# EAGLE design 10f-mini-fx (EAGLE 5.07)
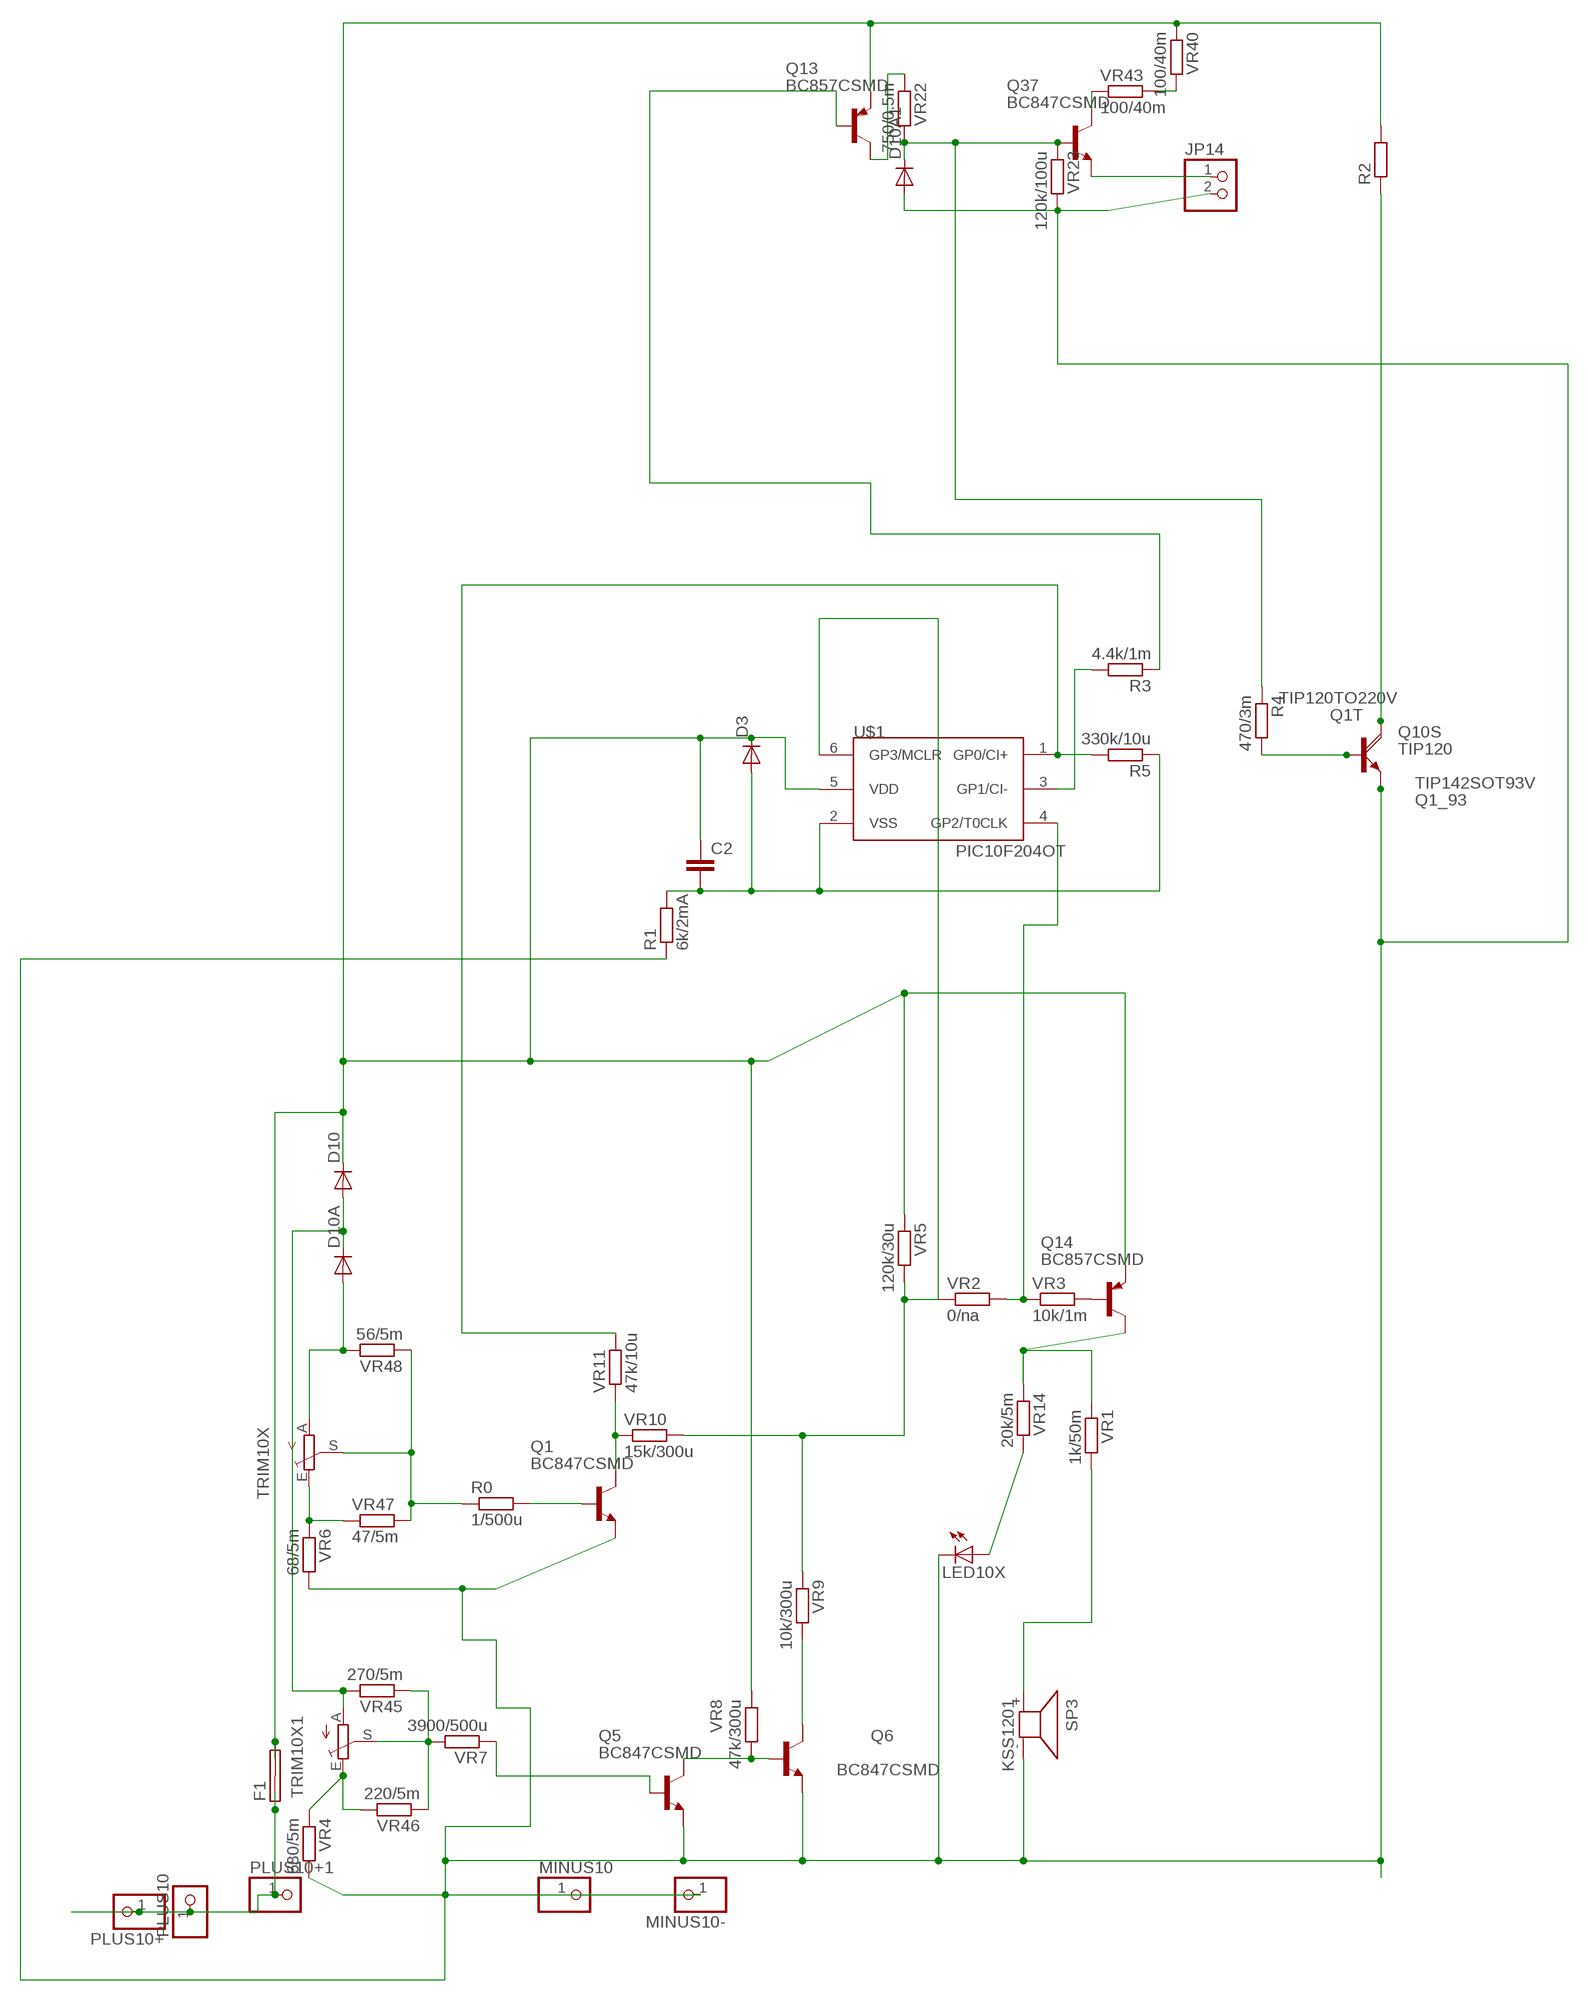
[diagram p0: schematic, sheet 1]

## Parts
C2  C-EUC0805  [C0805]
D3  DIODE-MINIMELF  [MINIMELF]
D10  DIODE-MINIMELF  [MINIMELF]
D10A  DIODE-MINIMELF  [MINIMELF]
D10A1  DIODE-MINIMELF  [MINIMELF]
F1  SHK20L7MM5  [7MM5]
JP14  PINHD-1X2STR  [1X02]
LED10X  LEDCHIPLED_1206  [CHIPLED_1206]
MINUS10  PINHD-1X14.5MM  [1X4MM5]
MINUS10-  PINHD-1X11X0.4  [1X01]
PLUS10  PINHD-1X14.5MM  [1X4MM5]
PLUS10+  PINHD-1X11X0.4  [1X01]
PLUS10+1  PINHD-1X11X0.4  [1X01]
Q1  BC847CSMD  [SOT23]
Q1_93  TIP142SOT93V  [SOT93V]
Q1T  TIP120TO220V  [TO220AV]
Q5  BC847CSMD  [SOT23]
Q6  BC847CSMD  [SOT23]
Q10S  TIP120  TIP120DPAK  [D-PAK_TO252AA]
Q13  BC857CSMD  [SOT23-BEC]
Q14  BC857CSMD  [SOT23-BEC]
Q37  BC847CSMD  [SOT23]
R0  1/500u  R-EU_R1206  [R1206]
R1  6k/2mA  R-EU_R0805  [R0805]
R2  R-EU_CERAM35  [CERAM35]
R3  4.4k/1m  R-EU_R1206  [R1206]
R4  470/3m  R-EU_R1206  [R1206]
R5  330k/10u  R-EU_R0805  [R0805]
SP3  KSS1201  KSS12017MM  [KSS1202]
TRIM10X  TRIM_EU-S64W  [S64W]
TRIM10X1  TRIM_EU-S64W  [S64W]
U$1  PIC10F204OT  [SOT23-6]
VR1  1k/50m  R-EU_R0805  [R0805]
VR2  0/na  R-EU_R0805  [R0805]
VR3  10k/1m  R-EU_R1206  [R1206]
VR4  680/5m  R-EU_R1206  [R1206]
VR5  120k/30u  R-EU_R0805  [R0805]
VR6  68/5m  R-EU_R1206  [R1206]
VR7  3900/500u  R-EU_M1206  [M1206]
VR8  47k/300u  R-EU_R1206  [R1206]
VR9  10k/300u  R-EU_R0805  [R0805]
VR10  15k/300u  R-EU_R1206  [R1206]
VR11  47k/10u  R-EU_R0805  [R0805]
VR14  20k/5m  R-EU_R0805  [R0805]
VR22  750/0.5m  R-EU_R0805  [R0805]
VR23  120k/100u  R-EU_R0805  [R0805]
VR40  100/40m  R-EU_R1206  [R1206]
VR43  100/40m  R-EU_R1206  [R1206]
VR45  270/5m  R-EU_R0805  [R0805]
VR46  220/5m  R-EU_R1206  [R1206]
VR47  47/5m  R-EU_R0805  [R0805]
VR48  56/5m  R-EU_R0805  [R0805]

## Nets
B: R0.1 TRIM10X.S VR47.2 VR48.1
BUZZ+: SP3.+ VR1.2
FPLUS: C2.1 D3.C D10.C F1.2A F1.2B Q13.E Q14.E R2.2 U$1.5(VDD) VR5.1 VR8.1 VR40.1
GP3: U$1.4(GP2/T0CLK) VR2.2 VR3.1
INPLUS: F1.1A F1.1B PLUS10+1.1 PLUS10+.1 PLUS10.1
N$1: R3.2 U$1.3(GP1/CI-)
N$2: Q1.3(C) VR10.1 VR11.1
N$3: Q5.3(C) Q6.1(B) VR8.2
N$4: LED10X.A VR14.2
N$5: Q6.3(C) VR9.2
N$6: U$1.6(GP3/MCLR) VR2.1 VR5.2 VR9.1 VR10.2
N$7: Q1.1(B) R0.2
N$8: Q14.C VR1.1 VR14.1
N$10: Q14.B VR3.2
N$14: D10A.A TRIM10X.A VR48.2
N$17: D10.A D10A.C TRIM10X1.A VR45.2
N$22: TRIM10X1.S VR7.2 VR45.1 VR46.1
N$23: Q13.B R3.1
N$24: TRIM10X1.E VR4.1 VR46.2
N$25: Q1_93.B Q1T.B Q10S.1(B) R4.2
N$128: TRIM10X.E VR6.1 VR47.1
N$136: JP14.1 Q37.2(E)
N$138: R5.2 U$1.1(GP0/CI+) VR11.2
N$159: Q13.C VR22.1
N$163: VR40.2 VR43.2
N$164: Q37.3(C) VR43.1
N$168: Q5.1(B) VR7.1
N$179: D10A1.C Q37.1(B) R4.1 VR22.2 VR23.1
Q10C: Q1_93.C Q1T.C Q10S.4(C) R2.1
VSS: D10A1.A JP14.2 LED10X.C MINUS10-.1 MINUS10.1 Q1.2(E) Q1_93.E Q1T.E Q5.2(E) Q6.2(E) Q10S.3(E) R1.1 SP3.- VR4.2 VR6.2 VR23.2
VSS1: C2.2 D3.A R1.2 R5.1 U$1.2(VSS)

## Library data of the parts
C2 = rcl:C-EU: CAPACITOR, European symbol
D3 D10 D10A D10A1 = diode:DIODE-: DIODE
F1 = fuse:SHK20L: FUSE HOLDER 5 x 20 mm, SH contact, SHH1 Schukat, E1073 Buerklin
JP14 = pinhead:PINHD-1X2: PIN HEADER
LED10X = led:LED: LED
MINUS10 MINUS10- PLUS10 PLUS10+ PLUS10+1 = pinhead:PINHD-1X1: PIN HEADER
Q1 Q5 Q6 Q37 = transistor-npn:BC847*: NPN Transistor
Q1_93 = transistor-power:TIP142: NPN DARLINGTON TRANSISTOR
Q1T Q10S = transistor-power:TIP120: NPN DARLINGTON TRANSISTOR
Q13 Q14 = transistor-pnp:BC857*: PNP Transistror
R0 R1 R3-R5 VR1-VR11 VR14 VR22 VR23 VR40 VR43 VR45-VR48 = rcl-2:R-EU_: RESISTOR, European symbol
R2 = rcl:R-EU_: RESISTOR, European symbol
SP3 = buzzer:KSS1201: SPEAKER
TRIM10X TRIM10X1 = pot:TRIM_EU-: POTENTIOMETER
U$1 = microchip-3:PIC10F2*: uPC nW 0,25/0,5k Program Flash memory Comparator

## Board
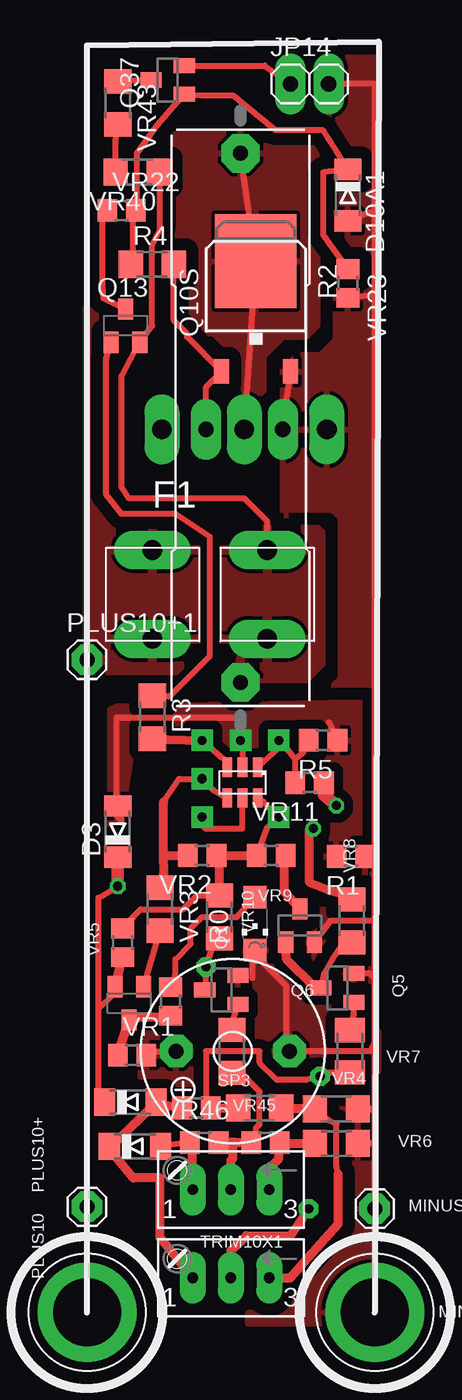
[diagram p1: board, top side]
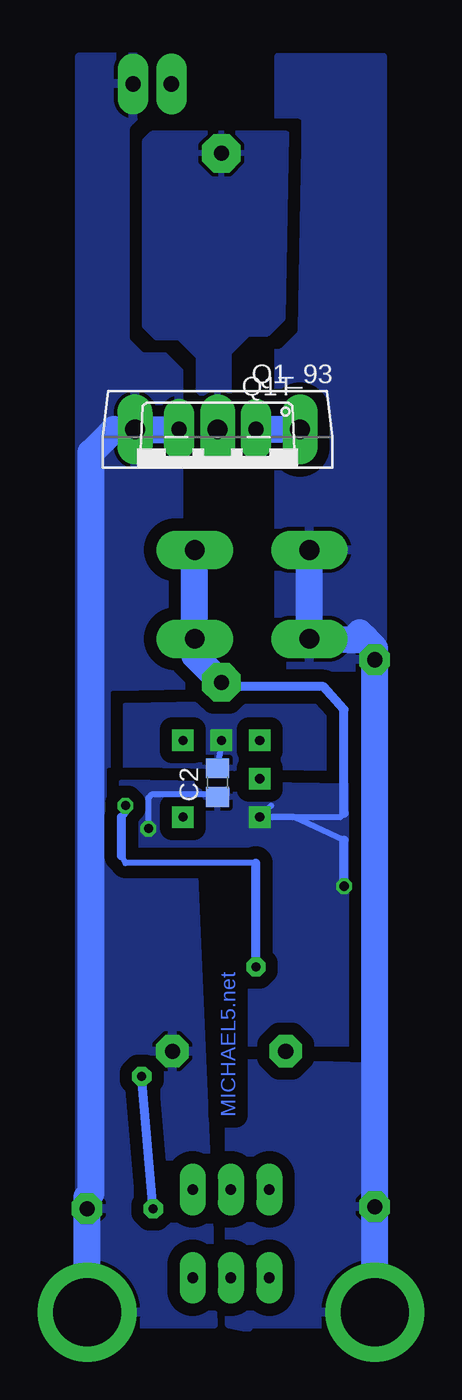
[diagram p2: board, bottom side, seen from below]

No outline drawn. Coordinates in mm, seen from the top.
Copper layers (1*16): Top 0.035mm / dielectric 1.5mm / Bottom 0.035mm
Design rules "default *": minimum track width 8mil, minimum drill 4mil, track to track 8mil, track to pad 8mil, pad to pad 8mil, via to via 8mil, smd to smd 8mil, copper to edge 40mil, drill to drill 8mil, minimum pad ring 20mil, minimum via ring 8mil, stop-mask expansion 4mil, vias tented up to drill 0mil, thermal gap 10mil

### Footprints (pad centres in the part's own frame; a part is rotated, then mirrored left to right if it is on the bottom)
C0805 = smd 1.3 x 1.5: 1 -0.95,0; 2 0.95,0
MINIMELF = smd 1.4 x 1.8: A 1.7,0; C -1.7,0
7MM5 = drill 1.3 pad 2.54 long: 1A -3.8,2.94; 1B -3.8,-2.94; 2A 3.8,2.94; 2B 3.8,-2.94
1X02 = drill 1.016 pad 1.676 long: 1 -1.27,0; 2 1.27,0
CHIPLED_1206 = smd 1.5 x 1.5: A 0,-1.75; C 0,1.75
1X4MM5 = drill 4.5 pad 6.35 round: 1 0,0
1X01 = drill 1 pad 1.676 octagon: 1 0,0
SOT23 = smd 1 x 1.4: 1 -0.95,-1.1; 2 0.95,-1.1; 3 0,1.1
SOT93V = drill 1.3 pad 1.676 long: B -5.461,-2.54; C 0,-2.54; E 5.461,-2.54
TO220AV = drill 1 pad 1.27 long: B -2.54,-2.54; C 0,-2.54; E 2.54,-2.54
D-PAK_TO252AA = smd 1 x 1.6: 1 -2.28,-4.8; 3 2.28,-4.8 | smd 5.4 x 6.2: 4 0,2.5
SOT23-BEC = smd 1 x 1.4: B -0.95,-1.1; C 0,1.1; E 0.95,-1.1
R1206 = smd 1.6 x 1.803: 1 -1.422,0; 2 1.422,0
R0805 = smd 1.3 x 1.5: 1 -0.95,0; 2 0.95,0
CERAM35 = drill 1 pad 2.54 octagon: 1 -17.5,0; 2 17.5,0
KSS1202 = drill 1 pad 2.159 octagon: + 3.75,0; - -3.75,0
S64W = drill 0.7 long: A 2.54,1.27; E -2.54,1.27; S 0,1.27
SOT23-6 = smd 0.635 x 1.27: 1 -1.016,-1.016; 2 0,-1.016; 3 1.016,-1.016; 4 1.016,1.016; 5 0,1.016; 6 -1.016,1.016
M1206 = smd 1.6 x 2: 1 -1.4,0; 2 1.4,0

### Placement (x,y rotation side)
C2  81.53,43.94 90 bottom
D3  73.15,40.7 90 top
D10  73.98,22.8 0 top
D10A  74.3,19.88 0 top
D10A1  88.39,82.8 270 top
F1  79.25,56.39 0 top
JP14  85.85,90.17 0 top
LED10X  82.23,34.61 180 top
MINUS10  90.17,8.89 0 top
MINUS10-  90.17,15.75 0 top
PLUS10  71.12,8.89 0 top
PLUS10+  71.12,15.88 0 top
PLUS10+1  71.12,52.07 0 top
Q1  80.01,30.23 90 top
Q1_93  81.53,64.77 180 bottom
Q1T  81.53,64.77 180 bottom
Q5  87.69,30.35 90 top
Q6  85.22,34.48 0 top
Q10S  82.3,75.95 0 top
Q13  73.66,74.17 0 top
Q14  73.91,29.34 180 top
Q37  76.45,90.42 90 top
R0  80.71,26.16 90 top
R1  88.58,39.05 180 top
R2  81.28,68.07 270 top
R3  75.44,48.26 270 top
R4  75.44,78.23 0 top
R5  86.74,46.74 180 top
SP3  80.77,26.16 180 top
TRIM10X  80.64,18.29 180 top
TRIM10X1  80.64,12.45 180 top
U$1  81.41,43.94 180 top
VR1  74.1,25.91 0 top
VR2  78.74,39.12 180 top
VR3  75.95,35.56 270 top
VR4  87.63,22.35 0 top
VR5  73.47,33.34 90 top
VR6  87.63,20.07 0 top
VR7  88.52,26.16 270 top
VR8  88.65,34.8 270 top
VR9  83.31,39.12 0 top
VR10  79.88,35.05 90 top
VR11  85.85,43.94 180 top
VR14  76.64,29.46 90 top
VR22  73.41,81.79 0 top
VR23  88.39,76.96 270 top
VR40  74.42,84.33 180 top
VR43  73.15,88.9 270 top
VR45  78.36,22.42 180 top
VR46  82.55,22.42 0 top
VR47  82.93,20.13 180 top
VR48  78.87,20.13 180 top

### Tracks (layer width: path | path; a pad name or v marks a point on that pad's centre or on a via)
B
  Top 0.406: VR47.2 82.3,20.45 82.3,21.08 82.55,21.34 82.55,23.5 81.18,24.87 R0.1 | 80.64,18.92 80.77,19.05
  Top 0.61: 81.03,20.13 VR48.1 | 81.03,20.13 VR47.2 | TRIM10X.S 80.64,18.92 | 80.77,19.05 80.77,19.88 81.03,20.13
BUZZ+
  Top 0.406: SP3.+ 74.86,26.16 VR1.2
  pour Top (isolate 0.61): 75.44,27.94 78.99,27.94 79.5,27.43 79.5,23.88 79.25,23.62 75.44,23.62 74.68,24.38 74.68,27.43
FPLUS  (via drill 0.6 pad 1.02, 0.6 pad 1.42)
  Top 0.406: 88.14,36.58 VR8.1 | U$1.5 81.41,40.89 78.99,40.89 78.74,41.15 v78.74,41.66 | D10.C 71.88,22.8 71.88,28.96 | 71.88,28.96 72.9,29.97 72.9,30.37 Q14.E | 71.88,28.96 71.88,36.32 v73.15,37.08 | VR40.1 75.95,83.46 75.95,80.52 75.44,79.5 75.44,74.17 74.61,73.09 Q13.E 73.41,70.85 73.41,63.5 73.91,62.74 81.53,62.74 83.05,61.22 F1.2A
  Top 0.61: 88.14,36.58 87.12,36.83 85.85,37.34 85.85,40.89 86.11,41.15 v86.11,40.89 | Q14.E VR5.1
  Top 0.813: v73.15,37.08 D3.C
  Bottom 0.406: C2.1 80.91,43.5 80.91,43.1 81.03,43.1 81.03,43.18 85.85,43.18 86.11,42.93 v86.11,40.89 | v78.74,41.66 77.98,42.42 | 73.15,40.13 76.45,41.66 v78.74,41.66 | 73.15,41.91 73.41,41.66 v78.74,41.66 | R2.2 80.8,50.57 80.52,50.29
  Bottom 0.61: v73.15,37.08 73.15,40.13 | 73.15,41.91 73.15,48.77 74.52,50.29 80.52,50.29
  Bottom 1.778: R2.2 83.05,52.34 F1.2B F1.2A
  pour Bottom (isolate 0.813): 72.9,43.69 87.88,43.94 87.88,37.85 79.76,37.85 79.76,26.67 72.39,26.67
  pour Top (isolate 0.406): 80.01,60.71 86.36,60.71 86.61,60.45 86.61,51.82 85.6,50.8 80.52,50.8 80.26,51.05
GP3  (via drill 0.6 pad 1.42)
  Top 0.406: U$1.4 79.5,43.43 v78.74,44.2 77.22,44.2 76.2,42.67
  Top 0.61: 76.2,39.12 76.2,42.67 | 76.2,39.12 VR2.2 | 76.2,39.12 76.2,37.93 VR3.1
INPLUS
  Bottom 1.778: 71.63,53.34 71.12,52.83 PLUS10+1.1 PLUS10+.1 PLUS10.1 | 71.63,53.34 72.14,53.85 | 71.63,53.34 F1.1B F1.1A
  pour Top (isolate 0.406): 71.37,60.45 78.49,60.45 78.74,60.2 78.74,52.58 77.47,51.31 71.37,51.31
  pour Bottom (isolate 0.813, rank 3): 71.63,24.64 71.63,25.15 80.77,25.4 80.77,8.13 79.5,7.87 79.5,8.13 71.37,8.13
  pour Bottom (isolate 0.813, rank 3): 77.47,52.58 77.47,91.95 77.22,91.95 70.61,91.95 70.61,52.32 70.87,52.32 71.12,52.32 71.12,51.56 76.71,51.56
  pour Top (isolate 0.813, rank 3): 77.47,52.58 77.47,91.95 71.12,91.95 71.12,52.32 71.12,52.32 71.12,51.56 76.71,51.56
N$1
  Top 0.406: 78.74,46.74 79.95,45.66 80.33,45.4 U$1.3
  Top 0.61: R3.2 78.74,46.74
N$2  (via drill 0.6 pad 1.02, 0.6 pad 1.27)
  Top 0.406: 86.8,43.11 VR11.1 | 79.88,33.15 VR10.1 79.5,33.25 v78.99,31.75 78.99,30.56 Q1.3
  Top 0.813: v87.63,42.42 86.8,43.11
  Bottom 0.406: 78.99,38.61 87.63,38.61 87.88,39.12 | 87.88,41.66 87.63,41.91 v87.63,42.42
  Bottom 0.61: v78.99,31.75 78.99,38.61 | 87.88,39.12 87.88,41.66
N$3
  Top 0.406: VR8.2 88.49,33.88 87.38,32.26 86.87,31.39 Q5.3
  Top 0.61: Q6.1 84.33,32.26 86.11,30.48 86.47,30.48 Q5.3
N$4
  Top 0.406: VR14.2 76.9,30.67 76.96,31.5 76.96,32.26 77.98,33.27 77.98,34.29 78.74,35.05 81.03,35.05 81.28,35.31 81.79,35.91 LED10X.A
N$5
  Top 0.406: 84.58,38.93 VR9.2
  Top 0.61: Q6.3 84.2,36.7 84.2,38.86 84.58,38.93
N$6
  Top 0.406: VR9.1 83.06,40.96 83.82,41.66 82.8,42.67 U$1.6 | VR10.2 78.38,36.47 77.47,35.56 74.68,35.56 74.17,35.05 73.66,34.55 VR5.2 | 79.88,38.92 VR2.1
  Top 0.61: VR2.1 VR9.1 | VR10.2 79.88,38.92
N$7
  Top 0.406: Q1.1 80.6,27.69 R0.2
N$8
  Top 0.406: 75.95,28.45 76.33,28.83 VR14.1 | Q14.C 74.32,28.45
  Top 0.61: 74.32,28.45 75.95,28.45 | VR1.1 Q14.C
N$9  (via drill 0.6 pad 1.42)
  other vias: 83.82,41.66
N$10
  Top 0.406: Q14.B 75.55,32.79 VR3.2
N$11  (via drill 0.6 pad 1.42)
  other vias: 83.82,46.74
N$14
  Top 0.406: 78.11,20.07 VR48.2 D10A.A
  Top 0.61: TRIM10X.A 78.11,20.07
N$17
  Top 0.406: 76.58,22.54 VR45.2
  Top 0.61: 76.58,22.54 D10.A 72.85,19.97 D10A.C 72.39,19.92 74.17,17.78 75.95,17.78 75.95,13.84 TRIM10X1.A
N$22  (via drill 0.6 pad 1.27)
  Top 0.406: VR45.1 78.99,22.42 78.99,26.16 82.55,26.16 82.55,25.4 83.69,24.26 85.6,24.26 v86.55,24.51 86.93,24.76 VR7.2
  Top 0.61: 78.99,22.42 VR46.1 | TRIM10X1.S 80.64,12.95 81.66,13.97 84.58,13.97 v85.79,15.75
  Bottom 0.61: v85.79,15.75 v86.55,24.51
N$23
  Top 0.406: R3.1 76.61,49.68 79.25,52.32 79.25,60.2 76.96,61.72 73.41,61.72 72.39,62.99 72.39,71.99 Q13.B
N$24
  Top 0.406: 87.76,18.03 87.63,18.54 87.63,21.34 87.12,21.59 86.46,22.1 VR4.1 | 84.03,22.35 VR46.2
  Top 0.61: TRIM10X1.E 84.58,11.18 85.47,12.19 87.76,14.73 87.76,18.03 | VR4.1 84.03,22.35
N$25
  Top 0.406: R4.2 76.86,74.52 77.72,73.66 77.72,73.44 Q10S.1 80.02,71.13 78.99,70.1 Q1T.B
  Bottom 1.778: Q1_93.B Q1T.B
N$128
  Top 0.406: 83.82,20.06 VR47.1 83.82,20.07
  Top 0.61: TRIM10X.E 83.19,18.41 83.82,19.05 83.82,20.06 | 83.82,20.07 VR6.1
N$136
  Top 0.406: Q37.2 82.87,91.37 JP14.1
N$138
  Top 0.406: 84.89,45.52 VR11.2 | 84.89,45.52 84.14,46.42 83.82,46.74 83.82,46.23 U$1.1 | R5.2 85.39,45.91 84.89,45.52
N$159
  Top 0.406: VR22.1 72.14,81.79 72.14,76.71 72.2,75.96 Q13.C
N$163
  Top 0.406: VR40.2 73,86.36 VR43.2
N$164
  Top 0.406: VR43.1 73.66,90.42 Q37.3
N$168
  Top 0.406: Q5.1 88.79,28.6 VR7.1
N$179
  Top 0.406: VR23.1 86.74,80.2 86.74,84.32 D10A1.C 86.69,87.12 83.57,87.12 80.77,89.41 78.67,89.41 Q37.1 75.78,87.46 74.42,85.6 74.42,82.11 VR22.2 74.17,81.79 74.17,78.23 R4.1
Q10C
  Top 0.406: R2.1 Q10S.4 Q1_93.C
  pour Top (isolate 0.813): 76.96,86.87 85.85,86.87 86.36,86.36 86.36,74.17 85.6,73.41 84.07,73.41 83.31,72.64 82.8,72.14 82.8,67.56 82.55,67.31 81.53,67.31 80.77,68.07 80.77,72.39 79.5,73.66 78.23,73.66 77.22,74.68
  pour Bottom (isolate 0.813): 76.96,86.87 85.85,86.87 86.36,86.36 86.36,74.17 85.6,73.41 84.07,73.41 83.31,72.64 82.8,72.14 82.8,67.56 82.55,67.31 81.53,67.31 80.77,68.07 80.77,72.39 79.5,73.66 78.23,73.66 77.22,74.68
VDF  (via drill 0.6 pad 1.42)
  other vias: 78.74,46.74
VSS
  Top 0.406: MINUS10.1 90.17,20.07 | 90.17,20.07 90.17,22.1 | VR4.2 89.92,22.35 90.17,22.1 | 90.17,20.07 VR6.2 | 90.04,26.54 90.17,26.42 90.17,22.1 | 90.04,26.54 89.92,26.16 SP3.- 84.33,26.36 84.33,30.48 82.23,32.58 LED10X.C 82.04,32.67 82.04,30.99 | Q5.2 89.86,31.3 90.17,30.99 | 90.17,30.99 90.17,26.67 90.04,26.54 | R1.1 89.92,39.12 90.17,38.86 | 90.17,30.99 90.17,34.8 | 90.17,34.8 90.17,38.86 | Q6.2 87.23,34.8 90.17,34.8 | JP14.2 90.17,90.17 90.17,81.79 | 90.17,38.86 90.17,76.2 | 90.17,76.2 90.17,81.79 | Q1T.E Q10S.3 | 90.17,81.79 D10A1.A | 90.17,76.2 VR23.2
  Bottom 1.778: MINUS10.1 MINUS10-.1 90.17,16.51 89.92,16.76 89.92,65.79 88.39,67.31 Q1_93.E Q1T.E
  pour Top (isolate 0.61): 81.53,33.53 81.53,31.5 80.52,30.48 80.52,28.7 84.58,24.64 90.17,24.64 90.42,24.89 90.42,27.43 89.66,28.19 87.12,28.19 87.12,30.99 85.6,31.75
  pour Bottom (isolate 0.813, rank 3): 84.84,91.95 90.68,91.95 90.68,8.13 81.79,8.13 84.07,60.71 84.07,84.84 85.09,84.84
  pour Top (isolate 0.813, rank 3): 84.84,91.95 90.17,91.95 90.17,8.13 81.79,8.13 84.07,60.71 84.07,84.84 85.09,84.84
VSS1  (via drill 0.6 pad 1.42)
  Top 0.406: U$1.2 81.41,46.48 v81.28,46.74 81.28,48.26 73.09,48.26 73.09,41.72 73.41,41.4 D3.A | R5.1 87.12,47.94
  Bottom 0.406: v81.28,46.74 C2.2
  pour Bottom (isolate 0.813, rank 2): 74.17,49.28 87.63,49.02 87.63,44.45 74.17,44.2
  pour Top (isolate 0.61): 72.64,41.15 72.64,48.77 73.15,49.02 89.15,49.28 89.15,39.05 88.39,38.86 86.87,38.86 86.87,45.47 87.38,46.23 87.38,46.74 86.87,47.24 83.31,47.24 82.3,46.23 80.26,46.23 80.26,46.48 79.5,47.24 74.68,47.24 74.17,46.74 73.41,41.66

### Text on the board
Bottom: MICHAEL5.net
